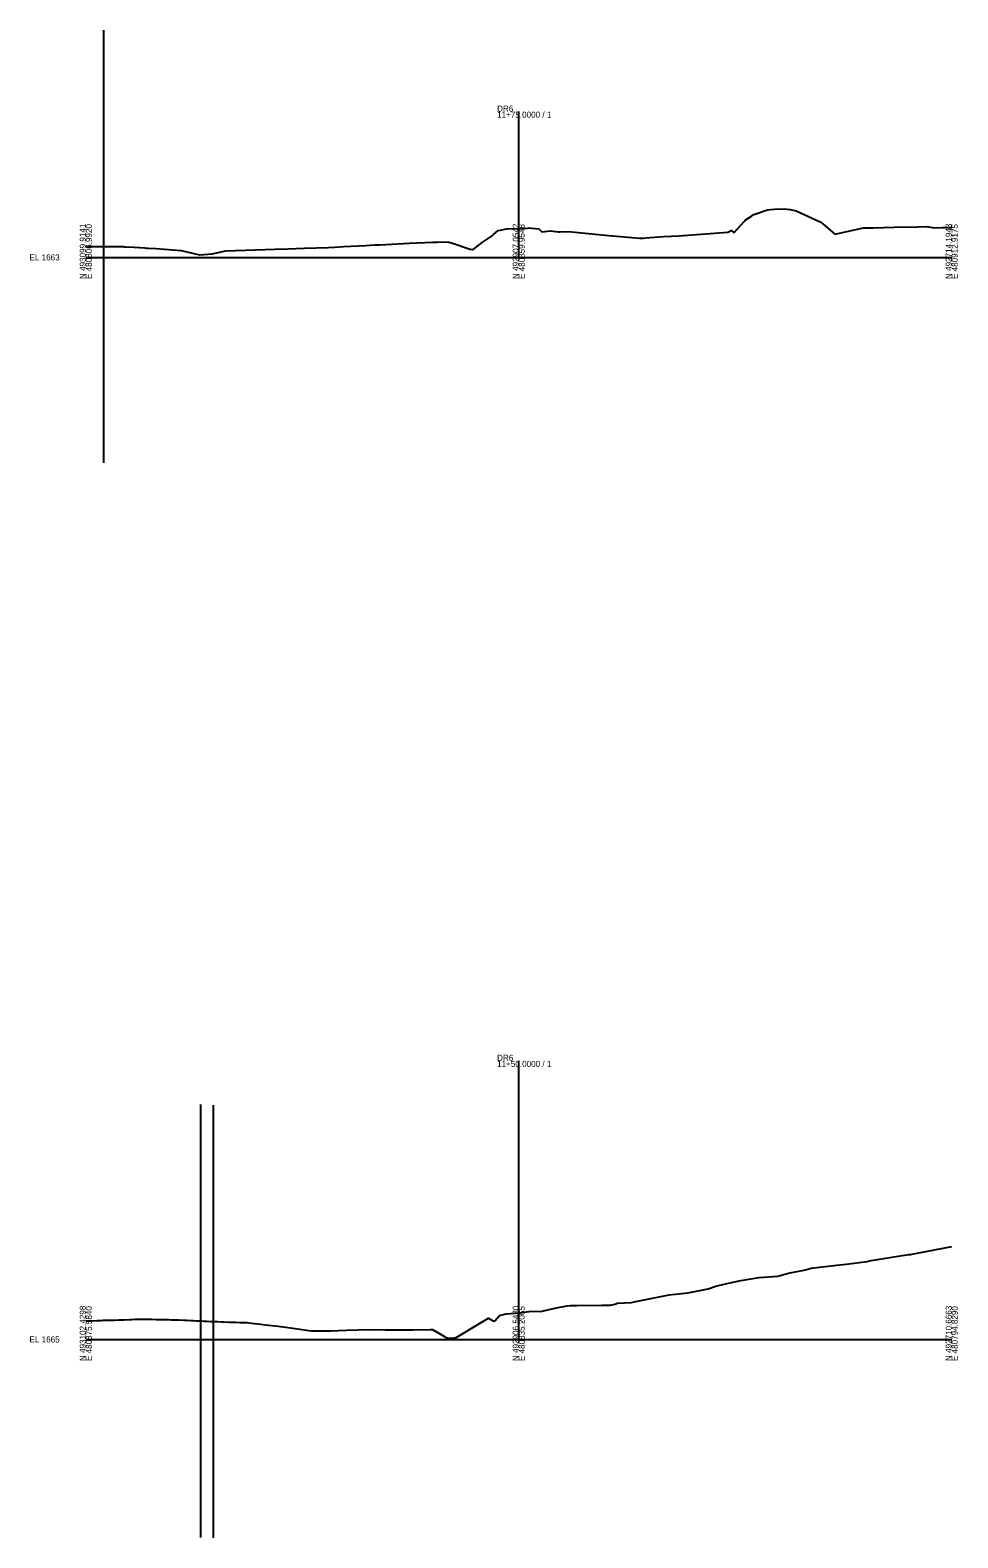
# Model space of a CAD drawing. Extents: x -26 to 403, y -88 to 5647.
# Drawn here: x -26 to 403, y 2908 to 3605 of the extents above; entities that cross this region are included whole.
import ezdxf

# ---------------------------------------------------------------- set-up
doc = ezdxf.new("R2010")
doc.units = 0
for name, color, linetype in [('Exist Cross Section Cell', 7, 'Continuous'), ('Exist XS Center Line Elevation Label', 7, 'Continuous'), ('Exist XS Ground Line', 7, 'Continuous'), ('Scratch_Level_7', 7, 'Continuous')]:
    doc.layers.add(name, color=color, linetype=linetype)

msp = doc.modelspace()

# ---------------------------------------------------------------- linework, layer by layer
at = {"layer": 'Exist Cross Section Cell'}
for p, q in [((200, 3500), (200, 3567.36)), ((0, 3500), (200, 3500)), ((200, 3500), (400, 3500)), ((200, 3000), (200, 3128.72)), ((0, 3000), (200, 3000)), ((200, 3000), (400, 3000))]:
    msp.add_line(p, q, dxfattribs=at)
at = {"layer": 'Exist XS Ground Line'}
for points in [[(0, 3505.04), (0.42, 3505.04), (2.31, 3505.03), (3.18, 3505.02), (4.68, 3505.02), (5.61, 3505.02), (6.5, 3505.02), (7.42, 3505.01), (7.95, 3505.01), (10.14, 3504.99), (12.13, 3504.99), (12.79, 3504.99), (13.85, 3504.99), (15.26, 3504.98), (17.44, 3504.96), (17.91, 3504.95), (18.41, 3504.95), (22.34, 3504.69), (27.25, 3504.38), (28.06, 3504.33), (28.9, 3504.25), (32.44, 3504.06), (44.01, 3503.14), (52.51, 3501.2), (58.37, 3501.68), (62.76, 3502.58), (63.94, 3502.83), (64.69, 3502.98), (87.33, 3503.74), (93.55, 3503.94), (101, 3504.26), (111.9, 3504.63), (114.95, 3504.74), (119.04, 3504.97), (129.41, 3505.48), (133.56, 3505.76), (136.01, 3505.85), (149.36, 3506.63), (160.22, 3506.99), (161.23, 3507.01), (162.39, 3507.06), (167.22, 3507.25), (169.86, 3506.4), (177.55, 3503.79), (178.59, 3503.63), (179.72, 3504.28), (183.17, 3506.82), (187.75, 3509.97), (188.33, 3510.57), (190.51, 3512.39), (191.38, 3512.59), (194.39, 3513.2), (200, 3513.41), (204.07, 3513.57), (205.16, 3513.61), (206.11, 3513.52), (209.25, 3513.19), (210.63, 3511.77), (214.74, 3512.29), (218.15, 3511.75), (219.13, 3511.81), (223.01, 3511.97), (240, 3510.28), (255.82, 3508.83), (257.64, 3508.93), (258.73, 3508.97), (266.93, 3509.73), (273.88, 3509.96), (296.58, 3511.7), (298.13, 3512.36), (299.15, 3511.6), (299.44, 3511.55), (301.01, 3513.18), (302.6, 3514.88), (304.36, 3516.75), (304.59, 3517.18), (307.56, 3519.06), (308.64, 3519.8), (309.03, 3519.93), (314.98, 3522.04), (318.05, 3522.23), (322.58, 3522.45), (325.33, 3522.06), (328.09, 3521.55), (339.21, 3516.5), (339.78, 3516.23), (340.54, 3515.47), (346, 3510.81), (346.72, 3510.85), (359.26, 3513.59), (363.79, 3513.66), (378.35, 3514.08), (380.44, 3514.03), (388.51, 3514.25), (391.79, 3513.73), (395.59, 3513.78), (400, 3513.83)], [(0, 3008.57), (1.61, 3008.61), (2.29, 3008.63), (2.71, 3008.65), (5.07, 3008.74), (7.33, 3008.82), (7.97, 3008.84), (9.98, 3008.89), (11.29, 3008.93), (12.53, 3008.95), (13.33, 3008.98), (15.06, 3009.03), (15.49, 3009.05), (17.69, 3009.13), (20.18, 3009.22), (21.28, 3009.26), (22.59, 3009.3), (23.13, 3009.32), (23.54, 3009.34), (24.54, 3009.38), (25.07, 3009.38), (26.61, 3009.38), (27.87, 3009.37), (28.2, 3009.37), (29.73, 3009.33), (30.38, 3009.31), (32.44, 3009.27), (33, 3009.26), (34.56, 3009.23), (35.49, 3009.21), (36.94, 3009.18), (38.01, 3009.16), (38.35, 3009.15), (39.49, 3009.13), (40.56, 3009.1), (42.03, 3009.06), (43.21, 3009.01), (45.19, 3008.92), (45.96, 3008.89), (46.8, 3008.84), (48.34, 3008.77), (49.83, 3008.7), (50.81, 3008.65), (51.45, 3008.63), (53.57, 3008.53), (54.49, 3008.49), (55.87, 3008.43), (57.77, 3008.36), (58.45, 3008.33), (59.92, 3008.27), (61.06, 3008.23), (62.73, 3008.16), (63.63, 3008.13), (66.06, 3008.03), (66.63, 3008.02), (67.79, 3007.98), (68.33, 3007.97), (68.75, 3007.96), (69.14, 3007.94), (71.18, 3007.88), (72.67, 3007.83), (73.31, 3007.81), (74.6, 3007.76), (76.56, 3007.54), (80.82, 3007.05), (82.8, 3006.82), (88.93, 3006.19), (95.58, 3005.14), (104.14, 3003.9), (109.24, 3003.93), (113.26, 3004), (120.42, 3004.29), (125.89, 3004.47), (132.85, 3004.53), (138.4, 3004.42), (150.4, 3004.5), (151.06, 3004.51), (159.03, 3004.52), (160.18, 3004.52), (165.74, 3001.41), (166.86, 3000.76), (167.3, 3000.67), (170.18, 3000.6), (170.4, 3000.76), (170.6, 3000.6), (183.48, 3008.27), (186.04, 3009.86), (188.55, 3008.42), (189.13, 3008.76), (191.05, 3011.12), (193.5, 3011.61), (194.45, 3011.77), (200, 3012.36), (200.92, 3012.45), (204.8, 3012.96), (205.87, 3013.04), (210.23, 3012.87), (214.68, 3013.94), (218.29, 3014.73), (222.33, 3015.48), (223.9, 3015.68), (226.84, 3015.74), (238.31, 3015.88), (242.39, 3015.89), (244.46, 3016.22), (245.66, 3016.69), (252.13, 3017.07), (253.35, 3017.37), (263.3, 3019.33), (269.52, 3020.58), (278.14, 3021.46), (283.69, 3022.59), (287.45, 3023.32), (291.09, 3024.65), (295.49, 3025.76), (296.97, 3026.07), (302.61, 3027.24), (309.95, 3028.47), (311.1, 3028.66), (319.7, 3029.31), (322.94, 3030.1), (324.59, 3030.57), (332.51, 3032.14), (335.08, 3032.96), (338.93, 3033.34), (347.01, 3034.37), (351.22, 3034.81), (360.96, 3036.07), (362.88, 3036.47), (380.07, 3039.23), (381.07, 3039.31), (382.36, 3039.49), (384.11, 3039.87), (400, 3042.91)]]:
    msp.add_lwpolyline(points, dxfattribs=at)
at = {"layer": 'Scratch_Level_7'}
for p, q in [((8.18, 3605.01), (8.18, 3405.01)), ((53.05, 3108.55), (53.05, 2908.55)), ((58.85, 3108.32), (58.85, 2908.32))]:
    msp.add_line(p, q, dxfattribs=at)

# ---------------------------------------------------------------- texts
at = {"layer": 'Exist Cross Section Cell'}
for s, p in [('11+75.0000 / 1', (190, 3564.56)), ('DR6', (190, 3567.36)), ('EL 1663', (-26, 3498.6)), ('11+50.0000 / 1', (190, 3125.92)), ('DR6', (190, 3128.72)), ('EL 1665', (-26, 2998.6))]:
    msp.add_text(s, height=2.8, dxfattribs=at).set_placement(p)
for s, p in [('N 493099.9141', (0, 3490)), ('E 480806.9920', (2.8, 3490)), ('N 492907.0542', (200, 3490)), ('E 480859.9548', (202.8, 3490)), ('N 492714.1943', (400, 3490)), ('E 480912.9175', (402.8, 3490)), ('N 493102.4298', (0, 2990)), ('E 480875.5840', (2.8, 2990)), ('N 492906.5480', (200, 2990)), ('E 480835.2065', (202.8, 2990)), ('N 492710.6663', (400, 2990)), ('E 480794.8290', (402.8, 2990))]:
    msp.add_text(s, height=2.8, rotation=90, dxfattribs=at).set_placement(p)
at = {"layer": 'Exist XS Center Line Elevation Label'}
for s, p in [('1676.41', (198.46, 3508.66)), ('1677.36', (198.29, 3007.61))]:
    msp.add_text(s, height=0.75, dxfattribs=at).set_placement(p)

doc.saveas('drawing.dxf')
